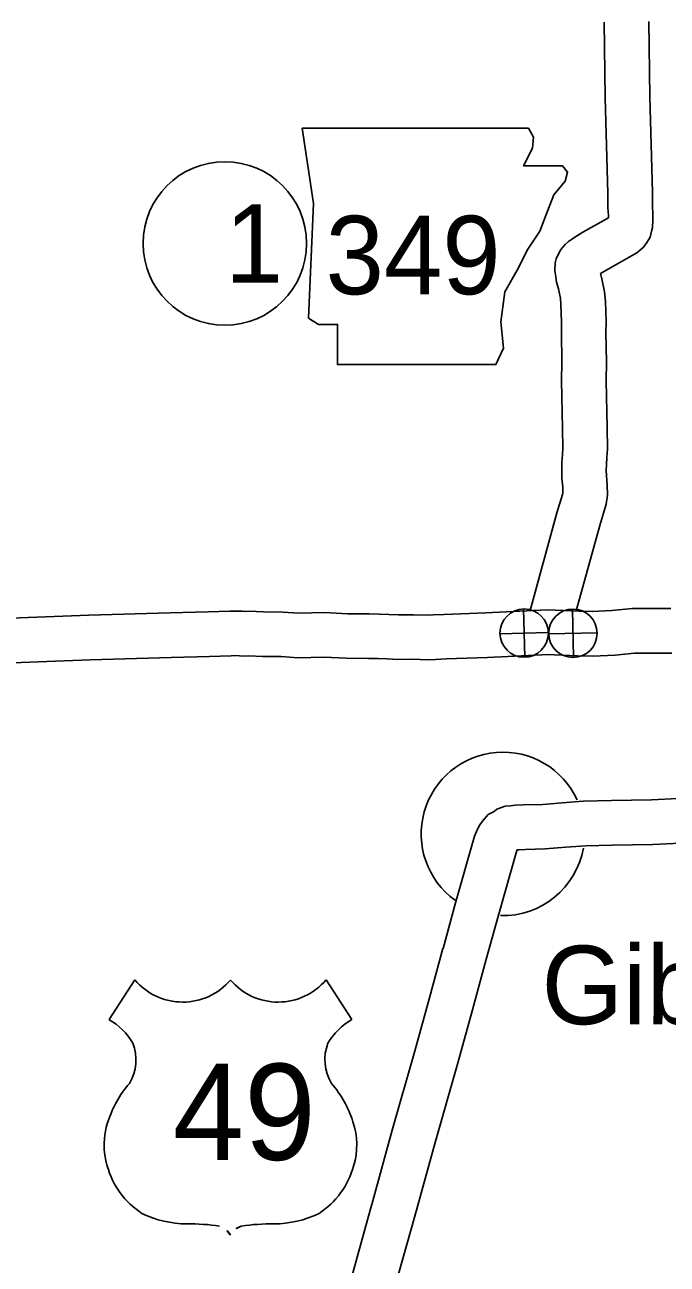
# Model space of a CAD drawing. Extents: x 1671357 to 13005564, y 567358 to 14261451.
# Drawn here: x 12758287.115 to 12758287.586, y 14259952.881 to 14259953.789 of the extents above; entities that cross this region are included whole.
import ezdxf

# ---------------------------------------------------------------- set-up
doc = ezdxf.new("R2010")
doc.units = 0
for name, color, linetype in [('10', 7, 'Continuous'), ('15', 7, 'Continuous'), ('21', 7, 'Continuous'), ('22', 7, 'Continuous'), ('24', 7, 'Continuous'), ('40', 7, 'Continuous')]:
    doc.layers.add(name, color=color, linetype=linetype)

msp = doc.modelspace()

# ---------------------------------------------------------------- linework, layer by layer
at = {"layer": '10'}
for points in [[(12758287.53958, 14259953.79043), (12758287.54037, 14259953.73503), (12758287.54217, 14259953.6652), (12758287.54233, 14259953.65465), (12758287.5426, 14259953.64877), (12758287.54262, 14259953.64746), (12758287.54262, 14259953.64723), (12758287.52379, 14259953.6365), (12758287.51795, 14259953.63304), (12758287.51635, 14259953.63171), (12758287.51559, 14259953.6312), (12758287.51347, 14259953.62972), (12758287.51102, 14259953.62769), (12758287.50917, 14259953.62565), (12758287.50802, 14259953.62412), (12758287.50643, 14259953.62184), (12758287.50435, 14259953.61711), (12758287.50351, 14259953.61412), (12758287.5033, 14259953.60836), (12758287.50383, 14259953.60557), (12758287.50407, 14259953.60359), (12758287.50466, 14259953.60005), (12758287.50536, 14259953.5976), (12758287.50597, 14259953.59514), (12758287.50749, 14259953.5881), (12758287.5078, 14259953.58393), (12758287.50826, 14259953.5708), (12758287.50815, 14259953.56278), (12758287.50855, 14259953.54154), (12758287.50827, 14259953.52772), (12758287.50907, 14259953.49307), (12758287.50923, 14259953.47841), (12758287.50897, 14259953.47366), (12758287.50862, 14259953.46781), (12758287.50843, 14259953.46266), (12758287.50854, 14259953.45629), (12758287.50912, 14259953.44974), (12758287.50919, 14259953.44576), (12758287.50901, 14259953.44441), (12758287.50489, 14259953.43093), (12758287.4853, 14259953.35943)], [(12758287.57225, 14259953.79093), (12758287.57304, 14259953.73568), (12758287.57483, 14259953.66587), (12758287.57499, 14259953.65566), (12758287.57526, 14259953.64976), (12758287.57529, 14259953.64779), (12758287.5753, 14259953.64596), (12758287.57504, 14259953.63982), (12758287.57427, 14259953.63735), (12758287.57335, 14259953.63287), (12758287.57073, 14259953.62893), (12758287.56841, 14259953.62569), (12758287.56346, 14259953.62149), (12758287.5402, 14259953.60825), (12758287.53687, 14259953.60627), (12758287.5378, 14259953.60252), (12758287.53989, 14259953.5928), (12758287.54043, 14259953.58574), (12758287.54094, 14259953.57115), (12758287.54083, 14259953.56287), (12758287.54123, 14259953.54152), (12758287.54095, 14259953.52776), (12758287.54173, 14259953.49363), (12758287.54191, 14259953.47769), (12758287.54158, 14259953.47181), (12758287.54126, 14259953.46626), (12758287.54111, 14259953.46232), (12758287.54119, 14259953.45799), (12758287.54176, 14259953.45148), (12758287.5419, 14259953.44388), (12758287.54103, 14259953.43742), (12758287.53628, 14259953.42184), (12758287.5191, 14259953.35914)], [(12758287.09178, 14259953.35337), (12758287.16179, 14259953.35604), (12758287.22137, 14259953.35768), (12758287.24932, 14259953.35839), (12758287.26527, 14259953.35902), (12758287.27029, 14259953.35907), (12758287.27412, 14259953.35886), (12758287.27582, 14259953.35874), (12758287.27921, 14259953.35885), (12758287.28987, 14259953.35839), (12758287.30396, 14259953.35833), (12758287.31579, 14259953.35759), (12758287.33484, 14259953.35794), (12758287.35131, 14259953.35711), (12758287.36723, 14259953.357), (12758287.3747, 14259953.35689), (12758287.38175, 14259953.3566), (12758287.38877, 14259953.35631), (12758287.39976, 14259953.35638), (12758287.40987, 14259953.35596), (12758287.41415, 14259953.35621), (12758287.42225, 14259953.35659), (12758287.45272, 14259953.35769), (12758287.49774, 14259953.35991)], [(12758287.49774, 14259953.35992), (12758287.52109, 14259953.35887), (12758287.53061, 14259953.35871), (12758287.54509, 14259953.35934), (12758287.56016, 14259953.36094), (12758287.58837, 14259953.36081)], [(12758287.49716, 14259953.32724), (12758287.52008, 14259953.32621), (12758287.53104, 14259953.32603), (12758287.54753, 14259953.32674), (12758287.56182, 14259953.32826), (12758287.58914, 14259953.32814)], [(12758287.09291, 14259953.32071), (12758287.16286, 14259953.32339), (12758287.22223, 14259953.32502), (12758287.25039, 14259953.32573), (12758287.26606, 14259953.32636), (12758287.26953, 14259953.32639), (12758287.27214, 14259953.32624), (12758287.27524, 14259953.32604), (12758287.27903, 14259953.32615), (12758287.2891, 14259953.32572), (12758287.30288, 14259953.32567), (12758287.31507, 14259953.3249), (12758287.33431, 14259953.32526), (12758287.35036, 14259953.32444), (12758287.36689, 14259953.32433), (12758287.3738, 14259953.32423), (12758287.38039, 14259953.32396), (12758287.3882, 14259953.32363), (12758287.3992, 14259953.32371), (12758287.41014, 14259953.32325), (12758287.41585, 14259953.32358), (12758287.42361, 14259953.32395), (12758287.45411, 14259953.32505), (12758287.4987, 14259953.32724)]]:
    msp.add_lwpolyline(points, dxfattribs=at)
at = {"layer": '15'}
for points in [[(12758287.59345, 14259953.22168), (12758287.5741, 14259953.22066), (12758287.54484, 14259953.22032), (12758287.52425, 14259953.21981), (12758287.50878, 14259953.21852), (12758287.49467, 14259953.21739), (12758287.4802, 14259953.21715), (12758287.47429, 14259953.21675), (12758287.47089, 14259953.21642), (12758287.46705, 14259953.21612), (12758287.46089, 14259953.2138), (12758287.45899, 14259953.21225), (12758287.45439, 14259953.20993), (12758287.45026, 14259953.20521), (12758287.44834, 14259953.20242), (12758287.44661, 14259953.19934), (12758287.44452, 14259953.19415), (12758287.43062, 14259953.14518), (12758287.42141, 14259953.1118)], [(12758287.59522, 14259953.18905), (12758287.57514, 14259953.188), (12758287.54543, 14259953.18766), (12758287.52601, 14259953.18717), (12758287.51144, 14259953.18596), (12758287.49626, 14259953.18474), (12758287.48158, 14259953.18449), (12758287.47696, 14259953.18418), (12758287.47568, 14259953.18406), (12758287.47548, 14259953.18357), (12758287.46209, 14259953.13637), (12758287.4529, 14259953.10311)], [(12758287.36919, 14259952.92441), (12758287.3842, 14259952.97868), (12758287.40062, 14259953.03594), (12758287.41148, 14259953.07566), (12758287.4214, 14259953.11178)], [(12758287.40068, 14259952.9157), (12758287.41565, 14259952.96982), (12758287.43209, 14259953.02713), (12758287.44299, 14259953.06703), (12758287.45291, 14259953.10312)], [(12758287.35448, 14259952.87164), (12758287.3692, 14259952.92444)], [(12758287.26007, 14259952.50268), (12758287.26177, 14259952.50803), (12758287.26244, 14259952.50914), (12758287.26319, 14259952.51017), (12758287.26646, 14259952.51571), (12758287.26867, 14259952.52086), (12758287.28398, 14259952.55714), (12758287.29969, 14259952.59402), (12758287.30141, 14259952.59846), (12758287.30324, 14259952.60135), (12758287.30439, 14259952.60359), (12758287.30579, 14259952.60628), (12758287.30758, 14259952.61038), (12758287.32134, 14259952.6437), (12758287.33684, 14259952.68149), (12758287.33952, 14259952.68681), (12758287.34156, 14259952.69375), (12758287.34266, 14259952.70073), (12758287.34692, 14259952.72095), (12758287.35183, 14259952.74004), (12758287.36313, 14259952.78051), (12758287.37223, 14259952.81237), (12758287.38598, 14259952.86297), (12758287.40067, 14259952.91566)]]:
    msp.add_lwpolyline(points, dxfattribs=at)
at = {"layer": '21'}
msp.add_lwpolyline([(12758287.31829, 14259953.71278), (12758287.32658, 14259953.6575), (12758287.3229, 14259953.57367), (12758287.33027, 14259953.56907), (12758287.34409, 14259953.56907), (12758287.34409, 14259953.53959), (12758287.46016, 14259953.53959), (12758287.46569, 14259953.55156), (12758287.46385, 14259953.57091), (12758287.46661, 14259953.59302), (12758287.47674, 14259953.61052), (12758287.48319, 14259953.62342), (12758287.4924, 14259953.63724), (12758287.49793, 14259953.65198), (12758287.50254, 14259953.66395), (12758287.51083, 14259953.67408), (12758287.51267, 14259953.68053), (12758287.50899, 14259953.68514), (12758287.48043, 14259953.68514), (12758287.48688, 14259953.69804), (12758287.4878, 14259953.70633), (12758287.48398, 14259953.71269)], close=True, dxfattribs=at)
at = {"layer": '22'}
for p, q in [((12758287.19554, 14259953.08891), (12758287.17669, 14259953.05976)), ((12758287.33569, 14259953.08891), (12758287.35454, 14259953.05976))]:
    msp.add_line(p, q, dxfattribs=at)
for centre, radius, start, end in [((12758287.23064, 14259953.11845), 0.04587, 220.07504, 319.67012), ((12758287.30058, 14259953.11845), 0.04587, 220.32988, 319.92496), ((12758287.15206, 14259953.01744), 0.04897, 30.7809, 59.98827), ((12758287.37917, 14259953.01744), 0.04897, 120.01173, 149.2191), ((12758287.16283, 14259953.03036), 0.03357, 328.81046, 21.21077), ((12758287.36839, 14259953.03036), 0.03357, 158.78923, 211.18954), ((12758287.25062, 14259952.96154), 0.07832, 138.95648, 162.69135), ((12758287.2806, 14259952.96154), 0.07832, 17.30865, 41.04352), ((12758287.22477, 14259952.96796), 0.05175, 160.95764, 197.38186), ((12758287.30646, 14259952.96796), 0.05175, 342.61814, 19.04236), ((12758287.23319, 14259952.96811), 0.05988, 195.10743, 237.13119), ((12758287.29803, 14259952.96811), 0.05988, 302.86881, 344.89257), ((12758287.23431, 14259952.98697), 0.07689, 244.07708, 269.57785), ((12758287.29692, 14259952.98697), 0.07689, 270.42215, 295.92292), ((12758287.23609, 14259952.76925), 0.14085, 81.19416, 90.95387), ((12758287.2537, 14259952.89553), 0.0135, 28.03422, 72.98637), ((12758287.27753, 14259952.89553), 0.0135, 107.01363, 151.96578), ((12758287.29514, 14259952.76925), 0.14085, 89.04613, 98.80584)]:
    msp.add_arc(centre, radius, start, end, dxfattribs=at)
at = {"layer": '24'}
for start, end in [(24.68332, 234.28003), (268.42345, 350.02229)]:
    msp.add_arc((12758287.46531, 14259953.1958), 0.0599, start, end, dxfattribs=at)
at = {"layer": '40'}
for p, q in [((12758287.48131, 14259953.32517), (12758287.48049, 14259953.36062)), ((12758287.51705, 14259953.32505), (12758287.51623, 14259953.3605)), ((12758287.46318, 14259953.34248), (12758287.49863, 14259953.3433)), ((12758287.49892, 14259953.34237), (12758287.53437, 14259953.34318))]:
    msp.add_line(p, q, dxfattribs=at)
for centre, radius in [((12758287.26153, 14259953.62834), 0.0599), ((12758287.4809, 14259953.34289), 0.01773), ((12758287.51664, 14259953.34277), 0.01773)]:
    msp.add_circle(centre, radius, dxfattribs=at)

# ---------------------------------------------------------------- texts
at = {"layer": '21'}
msp.add_text('349', height=0.057502, dxfattribs=at).set_placement((12758287.33533, 14259953.59112))
at = {"layer": '22'}
msp.add_text('49', height=0.07044, dxfattribs=at).set_placement((12758287.22335, 14259952.95697))
at = {"layer": '24'}
msp.add_text('Gibson', height=0.057502, dxfattribs=at).set_placement((12758287.49362, 14259953.05638))
at = {"layer": '40'}
msp.add_text('1', height=0.0575, dxfattribs=at).set_placement((12758287.26153, 14259953.59959))

doc.saveas('drawing.dxf')
